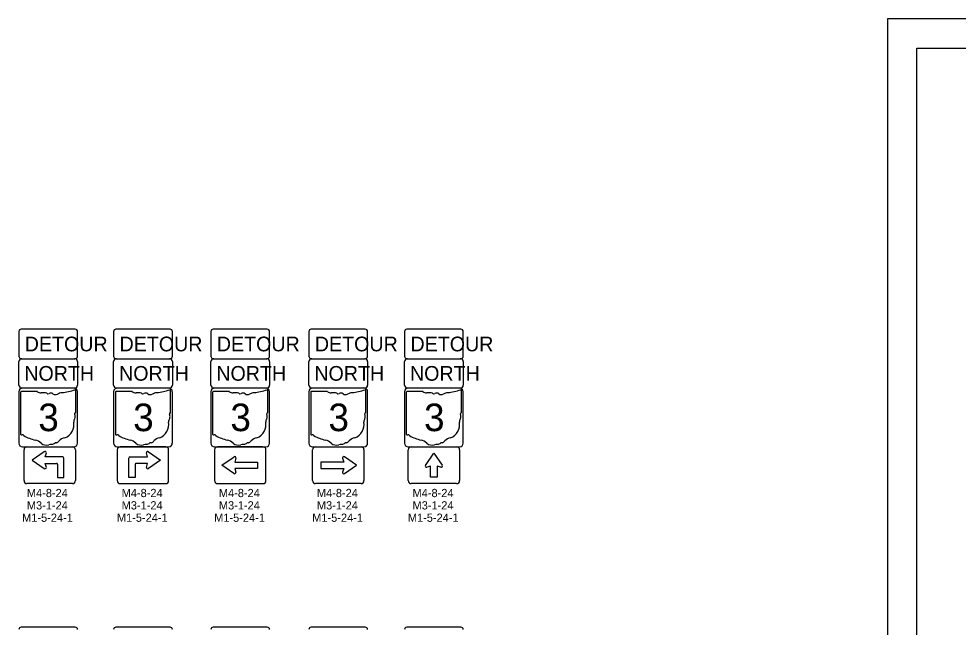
# Model space of a CAD drawing. Extents: x -15.3 to 34, y 0 to 22.
# Drawn here: x -14.79 to 1.2, y 11.65 to 22 of the extents above; entities that cross this region are included whole.
import ezdxf

# ---------------------------------------------------------------- set-up
doc = ezdxf.new("R2010")
doc.units = 0
for name, color, linetype in [('SC_Scratch1', 7, 'Continuous'), ('SH_Border', 7, 'Continuous'), ('SH_Cut_Line', 7, 'Continuous'), ('SN_P_Signs', 7, 'Continuous')]:
    doc.layers.add(name, color=color, linetype=linetype)

msp = doc.modelspace()

# ---------------------------------------------------------------- linework, layer by layer
at = {"layer": 'SH_Border'}
msp.add_lwpolyline([(0.5, 21.5), (1.5, 21.5), (1.5, 0.5), (0.5, 0.5)], close=True, dxfattribs=at)
at = {"layer": 'SH_Cut_Line'}
msp.add_lwpolyline([(0, 0), (34, 0), (34, 22), (0, 22)], close=True, dxfattribs=at)
at = {"layer": 'SN_P_Signs'}
for p, q in [((-14.79, 15.768), (-14.79, 16.168)), ((-14.74, 16.218), (-13.84, 16.218)), ((-13.79, 16.168), (-13.79, 15.768)), ((-13.176, 15.768), (-13.176, 16.168)), ((-13.126, 16.218), (-12.226, 16.218)), ((-12.176, 16.168), (-12.176, 15.768)), ((-11.521, 15.768), (-11.521, 16.168)), ((-11.471, 16.218), (-10.571, 16.218)), ((-10.521, 16.168), (-10.521, 15.768)), ((-9.852, 15.768), (-9.852, 16.168)), ((-9.802, 16.218), (-8.902, 16.218)), ((-8.852, 16.168), (-8.852, 15.768)), ((-8.224, 15.768), (-8.224, 16.168)), ((-8.174, 16.218), (-7.274, 16.218)), ((-7.224, 16.168), (-7.224, 15.768)), ((-13.84, 15.718), (-14.74, 15.718)), ((-13.822, 15.304), (-13.822, 15.676)), ((-12.226, 15.718), (-13.126, 15.718)), ((-12.208, 15.304), (-12.208, 15.676)), ((-10.571, 15.718), (-11.471, 15.718)), ((-10.553, 15.304), (-10.553, 15.676)), ((-8.902, 15.718), (-9.802, 15.718)), ((-8.884, 15.304), (-8.884, 15.676)), ((-7.274, 15.718), (-8.174, 15.718)), ((-7.256, 15.304), (-7.256, 15.676)), ((-14.76, 15.646), (-14.76, 14.935)), ((-14.476, 15.658), (-14.751, 15.658)), ((-13.146, 15.646), (-13.146, 14.935)), ((-12.862, 15.658), (-13.136, 15.658)), ((-11.49, 15.646), (-11.49, 14.935)), ((-11.207, 15.658), (-11.481, 15.658)), ((-9.821, 15.646), (-9.821, 14.935)), ((-9.538, 15.658), (-9.812, 15.658)), ((-8.193, 15.646), (-8.193, 14.935)), ((-7.91, 15.658), (-8.184, 15.658)), ((-13.823, 15.304), (-13.822, 15.304)), ((-12.208, 15.304), (-12.208, 15.304)), ((-10.553, 15.304), (-10.553, 15.304)), ((-8.884, 15.304), (-8.884, 15.304)), ((-7.256, 15.304), (-7.256, 15.304)), ((-14.651, 14.718), (-13.876, 14.718)), ((-12.289, 14.718), (-13.064, 14.718)), ((-10.633, 14.718), (-11.408, 14.718)), ((-10.633, 14.718), (-10.633, 14.718)), ((-9.739, 14.718), (-8.964, 14.718)), ((-8.111, 14.718), (-7.336, 14.718)), ((-14.701, 14.143), (-14.701, 14.668)), ((-14.356, 14.631), (-14.56, 14.492)), ((-14.341, 14.546), (-14.321, 14.617)), ((-13.826, 14.668), (-13.826, 14.143)), ((-13.114, 14.668), (-13.114, 14.143)), ((-12.598, 14.546), (-12.619, 14.617)), ((-12.583, 14.631), (-12.379, 14.492)), ((-12.239, 14.143), (-12.239, 14.668)), ((-11.458, 14.668), (-11.458, 14.143)), ((-10.583, 14.143), (-10.583, 14.668)), ((-9.789, 14.143), (-9.789, 14.668)), ((-8.914, 14.668), (-8.914, 14.143)), ((-8.161, 14.143), (-8.161, 14.668)), ((-7.866, 14.402), (-7.724, 14.609)), ((-7.724, 14.609), (-7.584, 14.405)), ((-7.286, 14.668), (-7.286, 14.143)), ((-14.56, 14.492), (-14.356, 14.352)), ((-14.044, 14.546), (-14.341, 14.546)), ((-14.321, 14.367), (-14.341, 14.437)), ((-14.341, 14.437), (-14.146, 14.437)), ((-14.13, 14.421), (-14.13, 14.195)), ((-14.044, 14.546), (-14.044, 14.546)), ((-14.021, 14.195), (-14.021, 14.523)), ((-12.918, 14.195), (-12.918, 14.523)), ((-12.895, 14.546), (-12.598, 14.546)), ((-12.895, 14.546), (-12.895, 14.546)), ((-12.809, 14.421), (-12.809, 14.195)), ((-12.598, 14.437), (-12.793, 14.437)), ((-12.619, 14.367), (-12.598, 14.437)), ((-12.379, 14.492), (-12.583, 14.352)), ((-11.333, 14.406), (-11.126, 14.548)), ((-11.129, 14.266), (-11.333, 14.406)), ((-11.095, 14.525), (-11.115, 14.46)), ((-11.115, 14.46), (-10.724, 14.46)), ((-10.724, 14.46), (-10.724, 14.351)), ((-9.258, 14.46), (-9.649, 14.46)), ((-9.649, 14.46), (-9.649, 14.351)), ((-9.278, 14.525), (-9.258, 14.46)), ((-9.039, 14.406), (-9.246, 14.548)), ((-9.243, 14.266), (-9.039, 14.406)), ((-10.724, 14.351), (-11.115, 14.351)), ((-11.115, 14.351), (-11.095, 14.287)), ((-9.649, 14.351), (-9.258, 14.351)), ((-9.258, 14.351), (-9.278, 14.287)), ((-7.779, 14.39), (-7.843, 14.37)), ((-7.779, 14.203), (-7.779, 14.39)), ((-7.605, 14.37), (-7.669, 14.39)), ((-7.669, 14.39), (-7.669, 14.203)), ((-13.876, 14.093), (-14.651, 14.093)), ((-14.13, 14.195), (-14.021, 14.195)), ((-14.13, 14.195), (-14.021, 14.195)), ((-13.064, 14.093), (-12.289, 14.093)), ((-12.809, 14.195), (-12.918, 14.195)), ((-11.408, 14.093), (-10.633, 14.093)), ((-8.964, 14.093), (-9.739, 14.093)), ((-7.336, 14.093), (-8.111, 14.093)), ((-7.669, 14.203), (-7.779, 14.203))]:
    msp.add_line(p, q, dxfattribs=at)
for points in [[(-14.79, 16.678), (-14.79, 16.258)], [(-13.83, 16.718), (-14.75, 16.718)], [(-13.79, 16.258), (-13.79, 16.678)], [(-13.176, 16.678), (-13.176, 16.258)], [(-12.216, 16.718), (-13.136, 16.718)], [(-12.176, 16.258), (-12.176, 16.678)], [(-11.521, 16.678), (-11.521, 16.258)], [(-10.561, 16.718), (-11.481, 16.718)], [(-10.521, 16.258), (-10.521, 16.678)], [(-9.852, 16.678), (-9.852, 16.258)], [(-8.892, 16.718), (-9.812, 16.718)], [(-8.852, 16.258), (-8.852, 16.678)], [(-8.224, 16.678), (-8.224, 16.258)], [(-7.264, 16.718), (-8.184, 16.718)], [(-7.224, 16.258), (-7.224, 16.678)], [(-14.75, 16.218), (-13.83, 16.218)], [(-13.136, 16.218), (-12.216, 16.218)], [(-11.481, 16.218), (-10.561, 16.218)], [(-9.812, 16.218), (-8.892, 16.218)], [(-8.184, 16.218), (-7.264, 16.218)], [(-13.853, 15.718), (-14.728, 15.718)], [(-12.239, 15.718), (-13.114, 15.718)], [(-10.583, 15.718), (-11.458, 15.718)], [(-8.914, 15.718), (-9.789, 15.718)], [(-7.286, 15.718), (-8.161, 15.718)], [(-14.79, 15.656), (-14.79, 14.781)], [(-13.79, 14.781), (-13.79, 15.656)], [(-13.176, 15.656), (-13.176, 14.781)], [(-12.176, 14.781), (-12.176, 15.656)], [(-11.521, 15.656), (-11.521, 14.781)], [(-10.521, 14.781), (-10.521, 15.656)], [(-9.852, 15.656), (-9.852, 14.781)], [(-8.852, 14.781), (-8.852, 15.656)], [(-8.224, 15.656), (-8.224, 14.781)], [(-7.224, 14.781), (-7.224, 15.656)], [(-14.728, 14.718), (-13.853, 14.718)], [(-13.114, 14.718), (-12.239, 14.718)], [(-11.458, 14.718), (-10.583, 14.718)], [(-9.789, 14.718), (-8.914, 14.718)], [(-8.161, 14.718), (-7.286, 14.718)], [(-13.83, 11.65), (-14.75, 11.65)], [(-12.216, 11.65), (-13.136, 11.65)], [(-10.561, 11.65), (-11.481, 11.65)], [(-8.892, 11.65), (-9.812, 11.65)], [(-7.264, 11.65), (-8.184, 11.65)]]:
    msp.add_lwpolyline(points, dxfattribs=at)
for centre, radius, start, end in [((-14.75, 16.678), 0.04, 90, 180), ((-13.83, 16.678), 0.04, 0, 90), ((-13.136, 16.678), 0.04, 90, 180), ((-12.216, 16.678), 0.04, 0, 90), ((-11.481, 16.678), 0.04, 90, 180), ((-10.561, 16.678), 0.04, 0, 90), ((-9.812, 16.678), 0.04, 90, 180), ((-8.892, 16.678), 0.04, 0, 90), ((-8.184, 16.678), 0.04, 90, 180), ((-7.264, 16.678), 0.04, 0, 90), ((-14.75, 16.258), 0.04, 180, 270), ((-14.74, 16.168), 0.05, 90, 180), ((-13.84, 16.168), 0.05, 0, 90), ((-13.83, 16.258), 0.04, 270, 0), ((-13.136, 16.258), 0.04, 180, 270), ((-13.126, 16.168), 0.05, 90, 180), ((-12.226, 16.168), 0.05, 0, 90), ((-12.216, 16.258), 0.04, 270, 0), ((-11.481, 16.258), 0.04, 180, 270), ((-11.471, 16.168), 0.05, 90, 180), ((-10.571, 16.168), 0.05, 0, 90), ((-10.561, 16.258), 0.04, 270, 0), ((-9.812, 16.258), 0.04, 180, 270), ((-9.802, 16.168), 0.05, 90, 180), ((-8.902, 16.168), 0.05, 0, 90), ((-8.892, 16.258), 0.04, 270, 0), ((-8.184, 16.258), 0.04, 180, 270), ((-8.174, 16.168), 0.05, 90, 180), ((-7.274, 16.168), 0.05, 0, 90), ((-7.264, 16.258), 0.04, 270, 0), ((-14.74, 15.768), 0.05, 180, 270), ((-14.728, 15.656), 0.0625, 90, 180), ((-14.156, 16.629), 0.994, 275.8445, 288.9065), ((-13.853, 15.656), 0.0625, 0, 90), ((-13.84, 15.768), 0.05, 270, 0), ((-13.833, 15.678), 0.0104, 351.8621, 97.738), ((-13.126, 15.768), 0.05, 180, 270), ((-13.114, 15.656), 0.0625, 90, 180), ((-12.542, 16.629), 0.994, 275.8445, 288.9065), ((-12.239, 15.656), 0.0625, 0, 90), ((-12.226, 15.768), 0.05, 270, 0), ((-12.219, 15.678), 0.0104, 351.8621, 97.738), ((-11.471, 15.768), 0.05, 180, 270), ((-11.458, 15.656), 0.0625, 90, 180), ((-10.887, 16.629), 0.994, 275.8445, 288.9065), ((-10.583, 15.656), 0.0625, 0, 90), ((-10.571, 15.768), 0.05, 270, 0), ((-10.563, 15.678), 0.0104, 351.8621, 97.738), ((-9.802, 15.768), 0.05, 180, 270), ((-9.789, 15.656), 0.0625, 90, 180), ((-9.218, 16.629), 0.994, 275.8445, 288.9065), ((-8.914, 15.656), 0.0625, 0, 90), ((-8.902, 15.768), 0.05, 270, 0), ((-8.894, 15.678), 0.0104, 351.8621, 97.738), ((-8.174, 15.768), 0.05, 180, 270), ((-8.161, 15.656), 0.0625, 90, 180), ((-7.59, 16.629), 0.994, 275.8445, 288.9065), ((-7.286, 15.656), 0.0625, 0, 90), ((-7.274, 15.768), 0.05, 270, 0), ((-7.266, 15.678), 0.0104, 351.8621, 97.738), ((-14.749, 15.648), 0.0109, 98.1301, 188.1301), ((-14.411, 15.741), 0.105, 231.6195, 271.1119), ((-14.376, 15.259), 0.378, 80.4867, 94.9883), ((-14.29, 15.651), 0.0304, 219.7921, 297.1024), ((-14.245, 15.569), 0.0632, 54.4667, 119.1411), ((-14.164, 15.682), 0.076, 233.8562, 294.8282), ((-14.03, 15.441), 0.2, 97.3462, 120.7689), ((-13.135, 15.648), 0.0109, 98.1301, 188.1301), ((-12.796, 15.741), 0.105, 231.6195, 271.1119), ((-12.762, 15.259), 0.378, 80.4867, 94.9883), ((-12.676, 15.651), 0.0304, 219.7921, 297.1024), ((-12.631, 15.569), 0.0632, 54.4667, 119.1411), ((-12.55, 15.682), 0.076, 233.8562, 294.8282), ((-12.415, 15.441), 0.2, 97.3462, 120.7689), ((-11.48, 15.648), 0.0109, 98.1301, 188.1301), ((-11.141, 15.741), 0.105, 231.6195, 271.1119), ((-11.106, 15.259), 0.378, 80.4867, 94.9883), ((-11.02, 15.651), 0.0304, 219.7921, 297.1024), ((-10.976, 15.569), 0.0632, 54.4667, 119.1411), ((-10.894, 15.682), 0.076, 233.8562, 294.8282), ((-10.76, 15.441), 0.2, 97.3462, 120.7689), ((-9.811, 15.648), 0.0109, 98.1301, 188.1301), ((-9.472, 15.741), 0.105, 231.6195, 271.1119), ((-9.437, 15.259), 0.378, 80.4867, 94.9883), ((-9.351, 15.651), 0.0304, 219.7921, 297.1024), ((-9.307, 15.569), 0.0632, 54.4667, 119.1411), ((-9.225, 15.682), 0.076, 233.8562, 294.8282), ((-9.091, 15.441), 0.2, 97.3462, 120.7689), ((-8.183, 15.648), 0.0109, 98.1301, 188.1301), ((-7.844, 15.741), 0.105, 231.6195, 271.1119), ((-7.809, 15.259), 0.378, 80.4867, 94.9883), ((-7.723, 15.651), 0.0304, 219.7921, 297.1024), ((-7.679, 15.569), 0.0632, 54.4667, 119.1411), ((-7.597, 15.682), 0.076, 233.8562, 294.8282), ((-7.463, 15.441), 0.2, 97.3462, 120.7689), ((-13.785, 15.148), 0.0705, 136.8065, 186.9296), ((-13.825, 15.277), 0.0162, 107.944, 210.337), ((-13.928, 15.23), 0.097, 340.033, 23.6496), ((-13.834, 15.302), 0.0112, 289.6038, 7.7341), ((-12.171, 15.148), 0.0705, 136.8065, 186.9296), ((-12.211, 15.277), 0.0162, 107.944, 210.337), ((-12.313, 15.23), 0.097, 340.033, 23.6496), ((-12.219, 15.302), 0.0112, 289.6038, 7.7341), ((-10.515, 15.148), 0.0705, 136.8065, 186.9296), ((-10.555, 15.277), 0.0162, 107.944, 210.337), ((-10.658, 15.23), 0.097, 340.033, 23.6496), ((-10.564, 15.302), 0.0112, 289.6038, 7.7341), ((-8.846, 15.148), 0.0705, 136.8065, 186.9296), ((-8.886, 15.277), 0.0162, 107.944, 210.337), ((-8.989, 15.23), 0.097, 340.033, 23.6496), ((-8.895, 15.302), 0.0112, 289.6038, 7.7341), ((-7.218, 15.148), 0.0705, 136.8065, 186.9296), ((-7.258, 15.277), 0.0162, 107.944, 210.337), ((-7.361, 15.23), 0.097, 340.033, 23.6496), ((-7.267, 15.302), 0.0112, 289.6038, 7.7341), ((-14.101, 15.101), 0.249, 292.3089, 8.9858), ((-12.486, 15.101), 0.249, 292.3089, 8.9858), ((-10.831, 15.101), 0.249, 292.3089, 8.9858), ((-9.162, 15.101), 0.249, 292.3089, 8.9858), ((-7.534, 15.101), 0.249, 292.3089, 8.9858), ((-14.749, 14.933), 0.011, 171.9584, 258.3066), ((-14.747, 15.006), 0.0836, 267.339, 280.6039), ((-14.73, 14.894), 0.0302, 29.7484, 93.2717), ((-14.35, 15.533), 0.718, 240.4129, 257.1985), ((-13.135, 14.933), 0.011, 171.9584, 258.3066), ((-13.133, 15.006), 0.0836, 267.339, 280.6039), ((-13.116, 14.894), 0.0302, 29.7484, 93.2717), ((-12.735, 15.533), 0.718, 240.4129, 257.1985), ((-11.479, 14.933), 0.011, 171.9584, 258.3066), ((-11.478, 15.006), 0.0836, 267.339, 280.6039), ((-11.461, 14.894), 0.0302, 29.7484, 93.2717), ((-11.08, 15.533), 0.718, 240.4129, 257.1985), ((-9.81, 14.933), 0.011, 171.9584, 258.3066), ((-9.809, 15.006), 0.0836, 267.339, 280.6039), ((-9.792, 14.894), 0.0302, 29.7484, 93.2717), ((-9.411, 15.533), 0.718, 240.4129, 257.1985), ((-8.183, 14.933), 0.011, 171.9584, 258.3066), ((-8.181, 15.006), 0.0836, 267.339, 280.6039), ((-8.164, 14.894), 0.0302, 29.7484, 93.2717), ((-7.783, 15.533), 0.718, 240.4129, 257.1985), ((-14.728, 14.781), 0.0625, 180, 270), ((-14.651, 14.668), 0.05, 90, 180), ((-14.564, 14.615), 0.225, 47.1842, 75.836), ((-14.321, 14.89), 0.143, 230.7004, 286.2918), ((-14.238, 14.644), 0.117, 85.6951, 111.2099), ((-14.228, 14.837), 0.0759, 268.777, 315.5493), ((-14.159, 14.768), 0.0214, 65.7517, 132.6484), ((-14.168, 14.866), 0.0803, 282.8732, 323.2771), ((-13.996, 14.735), 0.136, 94.4031, 142.5768), ((-13.876, 14.668), 0.05, 0, 90), ((-13.853, 14.781), 0.0625, 270, 0), ((-13.114, 14.781), 0.0625, 180, 270), ((-13.064, 14.668), 0.05, 90, 180), ((-12.949, 14.615), 0.225, 47.1842, 75.836), ((-12.706, 14.89), 0.143, 230.7004, 286.2918), ((-12.624, 14.644), 0.117, 85.6951, 111.2099), ((-12.614, 14.837), 0.0759, 268.777, 315.5493), ((-12.545, 14.768), 0.0214, 65.7517, 132.6484), ((-12.554, 14.866), 0.0803, 282.8732, 323.2771), ((-12.382, 14.735), 0.136, 94.4031, 142.5768), ((-12.289, 14.668), 0.05, 0, 90), ((-12.239, 14.781), 0.0625, 270, 0), ((-11.458, 14.781), 0.0625, 180, 270), ((-11.408, 14.668), 0.05, 90, 180), ((-11.294, 14.615), 0.225, 47.1842, 75.836), ((-11.051, 14.89), 0.143, 230.7004, 286.2918), ((-10.969, 14.644), 0.117, 85.6951, 111.2099), ((-10.958, 14.837), 0.0759, 268.777, 315.5493), ((-10.89, 14.768), 0.0214, 65.7517, 132.6484), ((-10.899, 14.866), 0.0803, 282.8732, 323.2771), ((-10.726, 14.735), 0.136, 94.4031, 142.5768), ((-10.633, 14.668), 0.05, 0, 90), ((-10.583, 14.781), 0.0625, 270, 0), ((-9.789, 14.781), 0.0625, 180, 270), ((-9.739, 14.668), 0.05, 90, 180), ((-9.625, 14.615), 0.225, 47.1842, 75.836), ((-9.382, 14.89), 0.143, 230.7004, 286.2918), ((-9.3, 14.644), 0.117, 85.6951, 111.2099), ((-9.289, 14.837), 0.0759, 268.777, 315.5493), ((-9.221, 14.768), 0.0214, 65.7517, 132.6484), ((-9.23, 14.866), 0.0803, 282.8732, 323.2771), ((-9.057, 14.735), 0.136, 94.4031, 142.5768), ((-8.964, 14.668), 0.05, 0, 90), ((-8.914, 14.781), 0.0625, 270, 0), ((-8.161, 14.781), 0.0625, 180, 270), ((-8.111, 14.668), 0.05, 90, 180), ((-7.997, 14.615), 0.225, 47.1842, 75.836), ((-7.754, 14.89), 0.143, 230.7004, 286.2918), ((-7.672, 14.644), 0.117, 85.6951, 111.2099), ((-7.661, 14.837), 0.0759, 268.777, 315.5493), ((-7.593, 14.768), 0.0214, 65.7517, 132.6484), ((-7.602, 14.866), 0.0803, 282.8732, 323.2771), ((-7.429, 14.735), 0.136, 94.4031, 142.5768), ((-7.336, 14.668), 0.05, 0, 90), ((-7.286, 14.781), 0.0625, 270, 0), ((-14.341, 14.617), 0.0209, 0.0017, 134.9999), ((-12.598, 14.617), 0.0209, 45.0001, 179.9983), ((-14.146, 14.421), 0.0156, 0, 90), ((-14.045, 14.523), 0.0234, 0, 90), ((-12.895, 14.523), 0.0234, 90, 180), ((-12.793, 14.421), 0.0156, 90, 180), ((-11.115, 14.531), 0.0209, 342.7954, 124.5888), ((-9.258, 14.531), 0.0209, 55.4112, 197.2046), ((-7.849, 14.39), 0.0209, 145.4112, 287.2046), ((-7.599, 14.39), 0.0209, 252.7954, 45.0096), ((-14.341, 14.367), 0.0209, 225.0001, 0.0017), ((-12.598, 14.367), 0.0209, 179.9983, 314.9999), ((-11.115, 14.281), 0.0209, 224.9904, 17.2046), ((-9.258, 14.281), 0.0209, 162.7954, 315.0096), ((-14.651, 14.143), 0.05, 180, 270), ((-13.876, 14.143), 0.05, 270, 360), ((-13.064, 14.143), 0.05, 180, 270), ((-12.289, 14.143), 0.05, 270, 0), ((-11.408, 14.143), 0.05, 180, 270), ((-10.633, 14.143), 0.05, 270, 0), ((-9.739, 14.143), 0.05, 180, 270), ((-8.964, 14.143), 0.05, 270, 360), ((-8.111, 14.143), 0.05, 180, 270), ((-7.336, 14.143), 0.05, 270, 0), ((-14.75, 11.61), 0.04, 90, 180), ((-13.83, 11.61), 0.04, 0, 90), ((-13.136, 11.61), 0.04, 90, 180), ((-12.216, 11.61), 0.04, 0, 90), ((-11.481, 11.61), 0.04, 90, 180), ((-10.561, 11.61), 0.04, 0, 90), ((-9.812, 11.61), 0.04, 90, 180), ((-8.892, 11.61), 0.04, 0, 90), ((-8.184, 11.61), 0.04, 90, 180), ((-7.264, 11.61), 0.04, 0, 90)]:
    msp.add_arc(centre, radius, start, end, dxfattribs=at)

# ---------------------------------------------------------------- texts
at = {"layer": 'SC_Scratch1'}
for s, p in [('M4-8-24', (-14.653, 13.863)), ('M4-8-24', (-13.039, 13.863)), ('M4-8-24', (-11.384, 13.863)), ('M4-8-24', (-9.715, 13.863)), ('M4-8-24', (-8.087, 13.863)), ('M3-1-24', (-14.653, 13.653)), ('M3-1-24', (-13.039, 13.653)), ('M3-1-24', (-11.384, 13.653)), ('M3-1-24', (-9.715, 13.653)), ('M3-1-24', (-8.087, 13.653)), ('M1-5-24-1', (-14.734, 13.443)), ('M1-5-24-1', (-13.12, 13.443)), ('M1-5-24-1', (-11.464, 13.443)), ('M1-5-24-1', (-9.795, 13.443)), ('M1-5-24-1', (-8.167, 13.443))]:
    msp.add_text(s, height=0.14, dxfattribs=at).set_placement(p)
at = {"layer": 'SN_P_Signs'}
for s, height, p in [('DETOUR', 0.25, (-14.689, 16.343)), ('DETOUR', 0.25, (-13.075, 16.343)), ('DETOUR', 0.25, (-11.419, 16.343)), ('DETOUR', 0.25, (-9.75, 16.343)), ('DETOUR', 0.25, (-8.122, 16.343)), ('NORTH', 0.25, (-14.697, 15.843)), ('NORTH', 0.25, (-13.083, 15.843)), ('NORTH', 0.25, (-11.428, 15.843)), ('NORTH', 0.25, (-9.759, 15.843)), ('NORTH', 0.25, (-8.131, 15.843)), ('3', 0.469, (-14.458, 14.985)), ('3', 0.469, (-12.843, 14.985)), ('3', 0.469, (-11.188, 14.985)), ('3', 0.469, (-9.519, 14.985)), ('3', 0.469, (-7.891, 14.985))]:
    msp.add_text(s, height=height, dxfattribs=at).set_placement(p)

doc.saveas('drawing.dxf')
